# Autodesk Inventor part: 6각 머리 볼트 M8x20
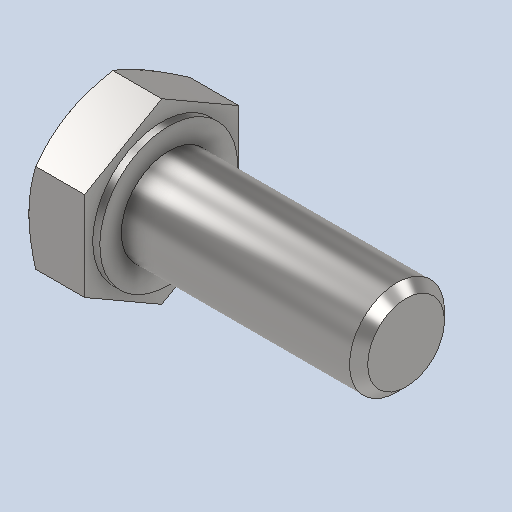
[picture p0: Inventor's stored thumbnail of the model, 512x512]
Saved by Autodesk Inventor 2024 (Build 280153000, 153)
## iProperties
Created: 2025-11
Part Number: 6각 머리 볼트 M8x20
Material: 강철, 연강
Description: 6각 머리 볼트 및 6각 머리 나사
Document SubType Name: Modeling
Designer: Eud07
Density: 7.85 g/cm^3
Appearance: 기본값
Author: jhkim
Sending System: Autodesk Inventor 2026
Preprocessor: ST-DEVELOPER v20.1
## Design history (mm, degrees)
node "6각 머리 볼트 M8x201"
node "솔리드1"
body "Solid1"
